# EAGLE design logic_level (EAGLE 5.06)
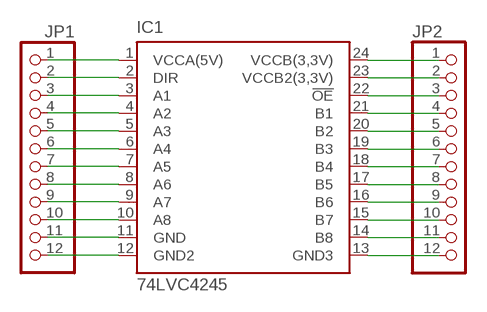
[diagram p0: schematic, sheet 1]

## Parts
IC1  74LVC4245  [SSOP24]
JP1  PINHD-1X12  [1X12]
JP2  PINHD-1X12  [1X12]

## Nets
N$1: IC1.1(VCCA(5V)) JP1.1
N$2: IC1.2(DIR) JP1.2
N$3: IC1.3(A1) JP1.3
N$4: IC1.4(A2) JP1.4
N$5: IC1.5(A3) JP1.5
N$6: IC1.6(A4) JP1.6
N$7: IC1.7(A5) JP1.7
N$8: IC1.8(A6) JP1.8
N$9: IC1.9(A7) JP1.9
N$10: IC1.10(A8) JP1.10
N$11: IC1.11(GND) JP1.11
N$12: IC1.12(GND2) JP1.12
N$13: IC1.24(VCCB(3,3V)) JP2.1
N$14: IC1.23(VCCB2(3,3V)) JP2.2
N$15: IC1.22(OE) JP2.3
N$16: IC1.21(B1) JP2.4
N$17: IC1.20(B2) JP2.5
N$18: IC1.19(B3) JP2.6
N$19: IC1.18(B4) JP2.7
N$20: IC1.17(B5) JP2.8
N$21: IC1.16(B6) JP2.9
N$22: IC1.15(B7) JP2.10
N$23: IC1.14(B8) JP2.11
N$24: IC1.13(GND3) JP2.12

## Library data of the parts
IC1 = sajat:74LVC4245: SN74LVC4245
JP1 JP2 = pinhead:PINHD-1X12: PIN HEADER

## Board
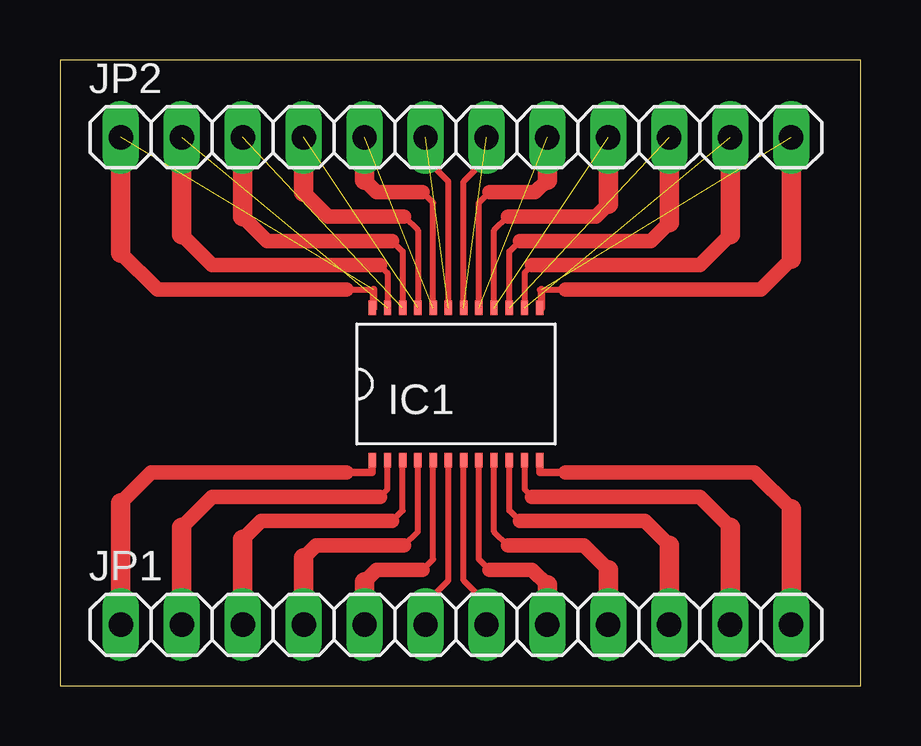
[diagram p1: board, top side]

Size 33.38 x 26.09 mm. Coordinates in mm from the lower left corner, seen from the top.
Outline: 0,0 33.38,0 33.38,26.09 0,26.09 0,0
Copper layers (1*16): Top 0.035mm / dielectric 1.5mm / Bottom 0.035mm
Design rules "default": minimum track width 10mil, minimum drill 24mil, track to track 8mil, track to pad 8mil, pad to pad 8mil, via to via 8mil, smd to smd 8mil, copper to edge 40mil, drill to drill 8mil, minimum pad ring 10mil, minimum via ring 8mil, stop-mask expansion 4mil, vias tented up to drill 0mil, thermal gap 10mil

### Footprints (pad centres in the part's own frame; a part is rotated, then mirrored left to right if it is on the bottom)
SSOP24 = smd 0.305 x 0.61: 1 -3.493,-2.54; 2 -2.857,-2.54; 3 -2.223,-2.54; 4 -1.587,-2.54; 5 -0.953,-2.54; 6 -0.318,-2.54; 7 0.318,-2.54; 8 0.953,-2.54; 9 1.587,-2.54; 10 2.223,-2.54; 11 2.857,-2.54; 12 3.493,-2.54; 13 3.493,3.81; 14 2.857,3.81; 15 2.223,3.81; 16 1.587,3.81; 17 0.953,3.81; 18 0.318,3.81; 19 -0.318,3.81; 20 -0.953,3.81; 21 -1.587,3.81; 22 -2.223,3.81; 23 -2.857,3.81; 24 -3.493,3.81
1X12 = drill 1.016 long: 1 -13.97,0; 2 -11.43,0; 3 -8.89,0; 4 -6.35,0; 5 -3.81,0; 6 -1.27,0; 7 1.27,0; 8 3.81,0; 9 6.35,0; 10 8.89,0; 11 11.43,0; 12 13.97,0

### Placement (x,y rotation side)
IC1  16.51,11.94 0 top
JP1  16.51,2.54 0 top
JP2  16.51,22.86 0 top

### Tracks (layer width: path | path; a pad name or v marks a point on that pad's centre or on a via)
N$1
  Top 0.305: 11.94,8.89 13.02,8.89 IC1.1
  Top 0.61: 11.94,8.89 3.81,8.89 2.54,7.62
  Top 0.813: JP1.1 2.54,7.62
N$2
  Top 0.254: IC1.2 13.65,8.19 13.34,7.87
  Top 0.61: 13.34,7.87 6.35,7.87 5.08,6.6
  Top 0.813: JP1.2 5.08,6.6
N$3
  Top 0.254: IC1.3 14.29,7.3 13.84,6.86
  Top 0.61: 13.84,6.86 8.38,6.86 7.62,6.1
  Top 0.813: JP1.3 7.62,6.1
N$4
  Top 0.254: IC1.4 14.92,6.41 14.35,5.84
  Top 0.61: 14.35,5.84 10.67,5.84 10.16,5.33
  Top 0.813: JP1.4 10.16,5.33
N$5
  Top 0.254: IC1.5 15.56,5.27 15.11,4.83
  Top 0.61: 15.11,4.83 13.21,4.83 12.7,4.32
  Top 0.813: JP1.5 12.7,4.32
N$6
  Top 0.254: IC1.6 16.19,4.38 15.24,3.43 JP1.6
N$7
  Top 0.254: IC1.7 16.83,4.38 17.78,3.43 JP1.7
N$8
  Top 0.254: IC1.8 17.46,5.27 17.91,4.83
  Top 0.61: 17.91,4.83 19.68,4.83 20.32,4.19
  Top 0.813: 20.32,4.19 JP1.8
N$9
  Top 0.254: IC1.9 18.1,6.41 18.67,5.84
  Top 0.61: 18.67,5.84 21.84,5.84 22.86,4.83
  Top 0.813: 22.86,4.83 JP1.9
N$10
  Top 0.254: IC1.10 18.73,7.3 19.18,6.86
  Top 0.61: 19.18,6.86 24.38,6.86 25.4,5.84
  Top 0.813: 25.4,5.84 JP1.10
N$11
  Top 0.254: IC1.11 19.37,8.19 19.68,7.87
  Top 0.61: 19.68,7.87 26.67,7.87 27.94,6.6
  Top 0.813: 27.94,6.6 JP1.11
N$12
  Top 0.305: 21.08,8.89 20,8.89 IC1.12
  Top 0.61: 21.08,8.89 28.96,8.89 30.48,7.37
  Top 0.813: 30.48,7.37 JP1.12
N$13  (1 unrouted)
  Top 0.305: IC1.24 13.08,15.75 13.08,16.51
N$14  (1 unrouted)
N$15  (1 unrouted)
N$16  (1 unrouted)
N$17  (1 unrouted)
N$18  (1 unrouted)
N$19  (1 unrouted)
N$20  (1 unrouted)
N$21  (1 unrouted)
N$22  (1 unrouted)
N$23  (1 unrouted)
N$24  (1 unrouted)
  Top 0.305: IC1.13 20.07,15.75 20.07,16.51
N$25
  Top 0.254: 20,16.51 21.08,16.51
  Top 0.61: 21.08,16.51 29.21,16.51 30.48,17.78
  Top 0.813: 30.48,17.78 30.48,22.86
N$26
  Top 0.254: 19.37,16 19.37,17.21 19.68,17.53
  Top 0.61: 19.68,17.53 26.67,17.53 27.94,18.8
  Top 0.813: 27.94,18.8 27.94,22.86
N$27
  Top 0.254: 18.73,15.88 18.73,18.1 19.18,18.54
  Top 0.61: 19.18,18.54 24.64,18.54 25.4,19.3
  Top 0.813: 25.4,19.3 25.4,22.86
N$28
  Top 0.254: 18.1,16 18.1,18.99 18.67,19.56
  Top 0.61: 18.67,19.56 22.35,19.56 22.86,20.07
  Top 0.813: 22.86,20.07 22.86,22.86
N$29
  Top 0.254: 17.46,16 17.46,20.13 17.91,20.57
  Top 0.61: 17.91,20.57 19.81,20.57 20.32,21.08
  Top 0.813: 20.32,21.08 20.32,22.86
N$30
  Top 0.254: 16.83,15.88 16.83,21.02 17.78,21.97 17.78,22.86
N$31
  Top 0.254: 16.19,16 16.19,21.02 15.24,21.97 15.24,22.86
N$32
  Top 0.254: 15.56,16 15.56,20.13 15.11,20.57
  Top 0.61: 15.11,20.57 13.21,20.57 12.7,21.08
  Top 0.813: 12.7,21.08 12.7,22.86
N$33
  Top 0.254: 14.92,16 14.92,18.99 14.35,19.56
  Top 0.61: 14.35,19.56 11.18,19.56 10.16,20.57
  Top 0.813: 10.16,20.57 10.16,22.86
N$34
  Top 0.254: 14.29,16 14.29,18.1 13.84,18.54
  Top 0.61: 13.84,18.54 8.64,18.54 7.62,19.56
  Top 0.813: 7.62,19.56 7.62,22.86
N$35
  Top 0.254: 13.65,16 13.65,17.21 13.34,17.53
  Top 0.61: 13.34,17.53 6.35,17.53 5.08,18.8
  Top 0.813: 5.08,18.8 5.08,22.86
N$36
  Top 0.254: 11.94,16.51 13.02,16.51
  Top 0.61: 11.94,16.51 4.06,16.51 2.54,18.03
  Top 0.813: 2.54,18.03 2.54,22.86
